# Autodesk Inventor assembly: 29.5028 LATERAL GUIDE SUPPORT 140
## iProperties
Created: 2007-07
Part Number: 29.5028 LATERAL GUIDE SUPPORT 140
Document SubType Name: Assembly
Designer: Andy Moles
Author: Andy Moles
